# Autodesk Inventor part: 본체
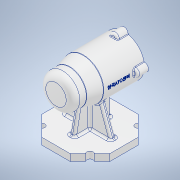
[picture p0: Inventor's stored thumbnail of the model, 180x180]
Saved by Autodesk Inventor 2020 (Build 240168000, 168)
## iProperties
Created: 2021-01
Part Number: 본체
Material: 알루미늄 6061
Document SubType Name: Modeling
Designer: USER
Density: 2.7 g/cm^3
Appearance: 알루미늄 - 평지
Mass: 629.962 g
Surface Area: 613.777 cm^2
Volume: 233.319 cm^3
Author: USER
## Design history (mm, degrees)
sketch "스케치1"
  geometry: L1 (0, 50)-(25, 50); L2 (25, 50)-(25, 30); L3 (25, 30)-(30, 10); L4 (30, 10)-(30, -50); L5 (30, -50)-(21, -50); L6 (21, -50)-(21, -35); L7 (21, -35)-(21, -35); L8 (24, -32)-(24, 4); L9 (21, 7)-(21, 7); L10 (21, 7)-(21, 18.7); L11 (20.7, 19)-(17.5, 19); L12 (17.5, 19)-(17.5, 36.7); L13 (17.2, 37)-(16, 37); L14 (16, 37)-(16, 40.7); L15 (15.7, 41)-(10.5, 41); L16 (10.5, 41)-(10.5, 41); L17 (7.5, 44)-(0, 44); L18 (0, 44)-(0, 50); A1 r 3 centre (21, 4) between (24, 4) and (21, 7); A2 r 3 centre (21, -32) between (21, -35) and (24, -32); A3 r 0.3 centre (15.7, 40.7) between (16, 40.7) and (15.7, 41); A4 r 0.3 centre (17.2, 36.7) between (17.5, 36.7) and (17.2, 37); A5 r 0.3 centre (20.7, 18.7) between (21, 18.7) and (20.7, 19); A6 r 3 centre (7.5, 41) between (10.5, 41) and (7.5, 44); 10 further points
  constraints: 36 end point, 14 perpendicular, 14 point on line, 12 point on circle, 12 tangent, 6 centre point, 3 equal radius, 1 horizontal, 1 parallel
  dimensions: "d0" = 100 distance between parallel lines of L5 L1; "d1" = 25 distance of L1.start L1.end; "d2" = 24 distance from line of point (0, 0) L8; "d3" = 21 distance from line of L6 point (0, 0); "d4" = 17.5 distance from line of point (0, 0) L12; "d5" = 16 distance from line of point (0, 0) L14; "d6" = 10.5 distance from line of point (0, 0) L16; "d7" = 0 distance from line of point (0, 0) L18; "d8" = 15 distance of L5.end L6.end; "d9" = 42 distance of point (24, -35) point (24, 7); "d10" = 12 distance of L9.end point (21, 19); "d11" = 18 distance of L11.end point (17.5, 37); "d12" = 4 distance of L13.end point (16, 41); "d13" = 3 distance of L15.end point (10.5, 44); "d14" = 40 distance from line of L3.end L1; "d15" = 20 distance of L1.end L2.end; "d16" = 30 horizontal distance of point (0, 0) L3.end; "d17" = 50 vertical distance of point (0, 0) L4.end; "d18" = 3 radius of A1; "d19" = 0.3 radius of A3; "d20" = 3 radius of A6
revolve "회전1" sketch "스케치1" stored, may be unused: angle "d21" = 90 deg
sketch "스케치2"
  geometry: C1 r 30 at (0, 0) reference; C2 r 6 at (30, 0); C3 r 6 at (0, 30); C4 r 6 at (-30, 0); C5 r 6 at (0, -30); 2 further points
  constraints: 4 centre point, 1 horizontal alignment, 10 other
  dimensions: "d22" = 12 diameter of C2; "d25" = 360 deg dimension on C1.centre C2.centre (derived); "d27" = 0 vertical distance of point (0, 0) C2.centre
extrude "돌출1" join sketch "스케치2" distance "d28" = 16; taper "d29" = 0 deg
sketch "스케치3"
  geometry: A1 r 30 centre (0, -30) between (29.4, -24.03) and (5.97, -0.6) reference; 5 further points
  constraints: 5 other
  dimensions: "d30" = 0 vertical distance of point (0, -30) point (30, -30); "d31" = 30 distance of point (0, -30) point (30, -30); "d34" = 360 deg dimension on A1.centre point (30, -30) (derived)
hole "구멍1" sketch "스케치3" at (30, -30), (0, 0), (-30, -30), (0, -60) diameter "d36" = 3.242; stored, may be unused: countersink angle "d40" = 90 deg, drill point angle "d42" = 118 deg; dims "d37" = 8, "d38" = 4, "d39" = 2, "d41" = 10
node "작업 평면1"
sketch "스케치4"
  geometry: L1 (20.711, 50)-(50, 20.711); L2 (50, 20.711)-(50, -20.711); L3 (50, -20.711)-(20.711, -50); L4 (20.711, -50)-(-20.711, -50); L5 (-20.711, -50)-(-50, -20.711); L6 (-50, -20.711)-(-50, 20.711); L7 (-50, 20.711)-(-20.711, 50); L8 (-20.711, 50)-(20.711, 50); C1 r 4.5 at (35.355, -35.355); C2 r 4.5 at (-35.355, -35.355); C3 r 4.5 at (-35.355, 35.355); C4 r 4.5 at (35.355, 35.355); 10 further points
  constraints: 16 end point, 4 centre point, 4 midpoint, 1 coincident, 17 other
  dimensions: "d46" = 50 horizontal distance of L5.end point (0, 0); "d47" = 50 horizontal distance of point (0, 0) L2.end; "d48" = 9 diameter of C1; "d49" = 9 diameter of C2; "d50" = 9 diameter of C3; "d51" = 9 diameter of C4
extrude "돌출2" join sketch "스케치4" distance "d52" = 10; taper "d53" = 0 deg
sketch "스케치6"
  geometry: L1 (-50, -75)-(-50, -65) reference; L2 (-38.537, -65)-(-50, -65) reference; L3 (50, -65)-(38.537, -65) reference; L4 (-19.314, -21.904)-(-35, -65); L5 (19.314, -21.904)-(35, -65); L6 (-35, -65)-(35, -65); L7 (50, -75)-(50, -65) reference; A1 r 29.204 centre (0, 0) between (-19.314, -21.904) and (19.314, -21.904); 1 further point
  constraints: 6 end point, 2 point on circle, 2 point on line, 1 centre point, 1 coincident, 1 collinear
  dimensions: "d64" = 110 deg angle of L4 L2; "d65" = 110 deg angle of L3 L5; "d66" = 15 distance from line of L4.end L1; "d67" = 15 distance from line of L7 L5.end; "d68" = 29.20353 radius of A1
extrude "돌출4" join sketch "스케치6" stored distance "d69" = 8; taper "d70" = 0 deg
sketch "스케치7"
  geometry: L1 (-65, -20.711)-(-65, 20.711) reference; L2 (-25.01, 19.227)-(-65, 27); L3 (-65, 27)-(-65, -27); L4 (-25.01, -27)-(-65, -27); L5 (-25.01, -27)-(-25.01, 19.227); L6 (-30, 10)-(-30, -34) reference; L7 (-75, 50)-(-65, 50) reference; L8 (-75, -50)-(-65, -50) reference; L9 (-65, 38.537)-(-65, 50) reference; 3 further points
  constraints: 8 end point, 2 point on line, 1 parallel, 1 perpendicular
  dimensions: "d75" = 23 distance from line of L2.end L7; "d76" = 23 distance from line of L8 L3.end; "d77" = 101 deg angle of L2 L9; "d79" = 46.22669 distance of L4.start L2.start
extrude "돌출5" join sketch "스케치7" stored distance "d80" = 8; taper "d81" = 0 deg
fillet "모깎기1" dims "d82" = 10
fillet "모깎기2" dims "d83" = 3
fillet "모깎기3" dims "d84" = 1
fillet "모깎기4" dims "d85" = 3
fillet "모깎기5" dims "d86" = 3
chamfer "모따기1" distance "d87" = 1; stored, may be unused: second distance "d88" = 2, angle "d89" = 45 deg
node "작업 평면2"
sketch "스케치8"
  geometry: L1 (30.171, -50)-(36, -50) reference; 2 further points
  constraints: 1 other
  dimensions: "d92" = 38 distance from line of L1 point (0, -12); "d93" = 0 horizontal distance of point (0, 0) point (0, -12)
feature "엠보싱1" sketch "스케치8" dims "d0" = 100, "d1" = 25, "d2" = 24, "d3" = 21, "d4" = 17.5, "d5" = 16, "d6" = 10.5, "d7" = 0, "d8" = 15, "d9" = 42, "d10" = 12, "d11" = 18, "d12" = 4, "d13" = 3, "d14" = 40, "d15" = 20, "d16" = 30, "d17" = 50, "d18" = 3, "d19" = 0.3, "d20" = 3, "d94" = 0.5, "d95" = 0
node "솔리드1"
feature "A9D066F2-1C7D-4E18-AEED-F7BC21143FA4" dims "d36" = 3.242, "d37" = 8, "d38" = 4, "d39" = 2, "d40" = 90 deg, "d41" = 10, "d42" = 118 deg
other parameters: "d43" = -75
